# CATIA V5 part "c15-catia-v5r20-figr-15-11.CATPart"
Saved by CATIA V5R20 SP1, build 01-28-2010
Part number: Part1
Bounding box of the stored display mesh (mm): x -50 to 50, y -32.5 to 33.5, z -52 to 1
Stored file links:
  D:\v5_r20\psrt_files_downloaded\c15\c15-catia-v5r20-figr-15-11.CATPart
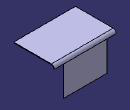
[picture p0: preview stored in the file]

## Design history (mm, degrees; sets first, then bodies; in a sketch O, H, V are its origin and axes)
SheetMetalParameters1: Thickness 1, BendRadius 4, KFactor 0.475772 {= log(min(100,max(20*SheetMetalParameters1.BendRadius,SheetMetalParameters1.Thickness)/SheetMetalParameters1.Thickness))/log(100)/2}, ReliefRadialLength 4, ReliefAxialLength 4, MinimumBendRadius 0
Body1 (main body)
  Sketch1 on xy-plane, origin (0, 0, 0), H (1, 0, 0), V (0, 1, 0)
    line L1 (-50, 32.5) -> (50, 32.5)
    line L2 (50, 32.5) -> (50, -32.5)
    line L3 (50, -32.5) -> (-50, -32.5)
    line L4 (-50, -32.5) -> (-50, 32.5)
    length L1 = 100
    length L2 = 65
    horizontal: L1 H, L3 H
    vertical: L2 V, L4 V
    symmetry: L4 L2 V, L1 L3 H
  Wall1: Thickness 1, Profile Sketch1
  d_NewWallOnEdge1: NewWallOnEdge_Edge edge [face of Wall1 | face of Wall1], NewWallOnEdge_Length 53, NewWallOnEdge_HeightLimitOffset 0, NewWallOnEdge_WidthOffset1 -15, NewWallOnEdge_WidthOffset2 -15, NewWallOnEdge_Angle 90, NewWallOnEdge_BendRadiusValue 4 {= SheetMetalParameters1.BendRadius}, NewWallOnEdge_BendTable SheetMetalParameters1, KFacteur 0.475772 {= log(min(100,max(20*d_NewWallOnEdge1.Radius,SheetMetalParameters1.Thickness)/SheetMetalParameters1.Thickness))/log(100)/2}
